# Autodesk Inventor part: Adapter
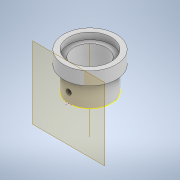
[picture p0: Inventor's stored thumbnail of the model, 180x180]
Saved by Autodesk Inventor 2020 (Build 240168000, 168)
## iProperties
Created: 2022-03
Part Number: Adapter
Material: Generic
Document SubType Name: Modeling
Designer: jonat
Density: 1 g/cm^3
Appearance: Default
Author: jonat
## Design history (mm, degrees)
sketch "Sketch1"
  geometry: C1 r 6.5 at (0, 0); 1 further point
  constraints: 1 centre point, 1 coincident
  dimensions: "d0" = 13 diameter of C1
sketch "Sketch2"
  geometry: C1 r 5 at (0, 0); 1 further point
  constraints: 1 centre point, 1 coincident
  dimensions: "d1" = 10 diameter of C1
extrude "Extrusion1" new body sketch "Sketch1" distance "d2" = 7; taper "d3" = 0 deg
sketch "Sketch3"
  geometry: C1 r 8 at (0, 0); 1 further point
  constraints: 1 centre point, 1 coincident
  dimensions: "d6" = 16 diameter of C1
extrude "Extrusion3" join sketch "Sketch3" distance "d7" = 4; taper "d8" = 0 deg
extrude "Extrusion2" cut sketch "Sketch2" distance "d4" = 100; taper "d5" = 0 deg
sketch "Sketch4"
  geometry: C1 r 6.45 at (0, 0); 1 further point
  constraints: 1 centre point, 1 coincident
  dimensions: "d9" = 12.9 diameter of C1
extrude "Extrusion4" cut sketch "Sketch4" distance "d10" = 2; taper "d11" = 0 deg
sketch "Sketch5"
  geometry: 3 further points
  constraints: 1 vertical alignment, 1 other
workplane "Work Plane1"
sketch "Sketch6"
  geometry: 2 further points
hole "Hole1" sketch "Sketch6" at (0, 3) diameter "d12" = 1.567; stored, may be unused: countersink angle "d16" = 90 deg, drill point angle "d18" = 118 deg; dims "d13" = 4, "d14" = 4, "d15" = 2, "d17" = 5
pattern_circular "Circular Pattern1" dims angle "d20" = 360 deg
body "Solid1"
